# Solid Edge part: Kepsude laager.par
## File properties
Author: KULL
Template: iso metric part.par
Last saved by: KULL
Revision: 3
Application: Solid Edge
Accuracy: 0,990
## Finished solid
Body 1: solid body, 10 faces, 12 edges, 0 vertices.
  Faces by surface: blend 4, cylinder 4, plane 2
  Edges by curve: intersection 8, circle 4
Bounding box of the edges (mm; curved faces can reach further): 4.000 x 4.000 x 4.000, from (-2, -2, -2) to (2, 2, 2).
Cylindrical faces by radius (mm): R0.3 x2, R1.5 x1, R2 x1
Planar faces by outward normal: +x 1, -x 1
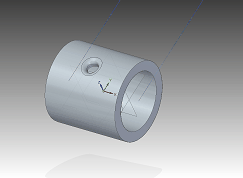
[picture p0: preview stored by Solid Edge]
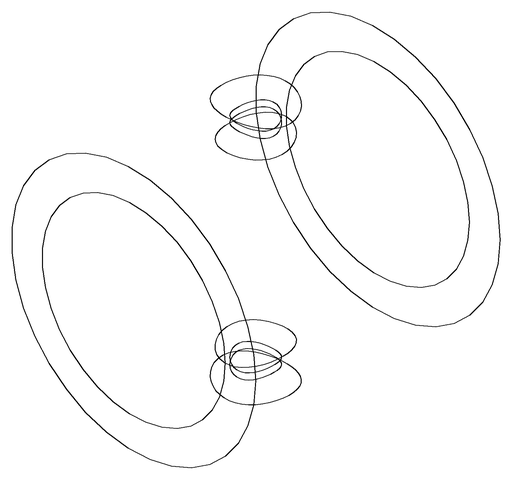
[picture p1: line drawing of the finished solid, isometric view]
